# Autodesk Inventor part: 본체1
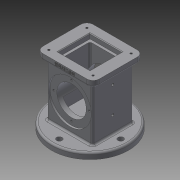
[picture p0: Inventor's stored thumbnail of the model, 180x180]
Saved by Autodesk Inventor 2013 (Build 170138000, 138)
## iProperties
Created: 2018-10
Part Number: 본체1
Material: Generic
Document SubType Name: Modeling
Designer: Administrator
Density: 1 g/cm^3
Author: Administrator
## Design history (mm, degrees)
sketch "스케치1"
  geometry: C1 r 62.5 at (0, 0); 1 further point
  constraints: 1 centre point, 1 coincident
extrude "돌출1" new body sketch "스케치1" distance "d1" = 10; taper "d2" = 0 deg
sketch "스케치2"
  geometry: C1 r 62.5 at (0, 0) reference; A1 r 50 centre (0, 0) between (0, 50) and (50, 0); 2 further points
  constraints: 4 point on circle, 1 centre point, 1 coincident
  dimensions: "d3" = 100 diameter of A1
hole "구멍1" sketch "스케치2" at (0, 50), (50, 0), (0, -50), (-50, 0) diameter "d4" = 9; stored, may be unused: countersink angle "d8" = 90 deg, drill point angle "d10" = 118 deg; dims "d5" = 6, "d6" = 4, "d7" = 2, "d9" = 8
sketch "스케치3"
  geometry: L1 (-37, 33)-(37, 33); L2 (37, 33)-(37, -33); L3 (37, -33)-(-37, -33); L4 (-37, -33)-(-37, 33); C1 r 62.5 at (0, 0) reference; 2 further points
  constraints: 8 end point, 2 midpoint, 2 parallel, 1 horizontal, 1 horizontal alignment, 1 perpendicular, 1 vertical alignment
  dimensions: "d11" = 74 distance of L1.start L1.end; "d13" = 66 distance of L1.end L2.end
extrude "돌출2" join sketch "스케치3" distance "d14" = 98; taper "d15" = 0 deg
sketch "스케치4"
  geometry: L1 (37, 33)-(-37, 33) reference; L2 (-37, 33)-(-37, -33) reference; L3 (-37, -33)-(37, -33) reference; L4 (37, -33)-(37, 33) reference; L5 (-46, 41)-(46, 41); L6 (46, 41)-(46, -41); L7 (46, -41)-(-46, -41); L8 (-46, -41)-(-46, 41); 3 further points
  constraints: 8 end point, 2 midpoint, 2 parallel, 1 horizontal, 1 horizontal alignment, 1 perpendicular, 1 vertical alignment
  dimensions: "d16" = 92 distance of L5.start L5.end; "d18" = 82 distance of L5.end L6.end
extrude "돌출3" join sketch "스케치4" distance "d19" = 10; taper "d20" = 0 deg
sketch "스케치5"
  geometry: L1 (-26, 26)-(26, 26); L2 (26, 26)-(26, -26); L3 (26, -26)-(-26, -26); L4 (-26, -26)-(-26, 26); 3 further points
  constraints: 8 end point, 2 midpoint, 2 parallel, 1 horizontal, 1 horizontal alignment, 1 perpendicular, 1 vertical alignment
  dimensions: "d21" = 52 distance of L1.start L1.end; "d23" = 52 distance of L1.end L2.end
extrude "돌출4" cut sketch "스케치5" distance "d24" = 8; taper "d25" = 0 deg
fillet "모깎기5" dims "d86" = 3
fillet "모깎기6" dims "d87" = 3
fillet "모깎기1" dims "d38" = 10
sketch "스케치8"
  geometry: L1 (-22, 22)-(22, 22); L2 (22, 22)-(22, -22); L3 (22, -22)-(-22, -22); L4 (-22, -22)-(-22, 22); 3 further points
  constraints: 8 end point, 2 midpoint, 2 parallel, 1 horizontal, 1 horizontal alignment, 1 perpendicular, 1 vertical alignment
  dimensions: "d39" = 44 distance of L1.end L2.end; "d41" = 44 distance of L1.start L1.end
extrude "돌출5" cut sketch "스케치8" distance "d42" = 74; taper "d43" = 0 deg
sketch "스케치7"
  geometry: L1 (-33, 54)-(33, 54); L2 (-62.5, 0)-(62.5, 0) reference; L3 (-33, 89)-(-30, 89); L4 (-30, 89)-(-30, 78); L5 (-30, 78)-(30, 78); L6 (30, 78)-(30, 89); L7 (30, 89)-(33, 89); L8 (33, 89)-(33, 99); L9 (-33, 99)-(-33, 89); L10 (-33, 89)-(-33, 54); L11 (33, 54)-(33, 89); 3 further points
  constraints: 20 end point, 5 parallel, 2 midpoint, 2 vertical alignment, 1 collinear, 1 horizontal, 1 perpendicular
  dimensions: "d28" = 54 distance between parallel lines of L2 L1; "d29" = 66 distance of L1.start L1.end; "d31" = 48 diameter of L5 L1; "d32" = 3 distance of L3.start L3.end; "d33" = 3 distance of L6.end L7.end; "d34" = 70 diameter of L7 L1; "d35" = 70 diameter of L3 L1; "d36" = 66 distance of L8.end L9.start; "d88" = 33 distance from line of L10 point (0, 54); "d89" = 33 distance from line of point (0, 54) L11 (derived)
revolve "회전1" sketch "스케치7" stored, may be unused: angle "d37" = 90 deg
fillet "모깎기2" dims "d44" = 3
sketch "스케치9"
  geometry: A1 r 10 centre (-36, -31) between (-46, -31) and (-36, -41) reference; A2 r 10 centre (36, -31) between (36, -41) and (46, -31) reference; A3 r 10 centre (36, 31) between (46, 31) and (36, 41) reference; A4 r 10 centre (-36, 31) between (-36, 41) and (-46, 31) reference; 1 further point
hole "구멍2" sketch "스케치9" at (-36, -31), (36, -31), (36, 31), (-36, 31) diameter "d45" = 3.242; stored, may be unused: countersink angle "d49" = 90 deg, drill point angle "d51" = 118 deg; dims "d46" = 4, "d47" = 4, "d48" = 2, "d50" = 8
sketch "스케치10"
  geometry: C1 r 35 at (0, 0) reference; A1 r 29 centre (0, 0) between (0, 29) and (29, 0); 3 further points
  constraints: 4 point on circle, 1 centre point, 1 coincident
  dimensions: "d52" = 58 diameter of A1
hole "구멍3" sketch "스케치10" at (0, 29), (29, 0), (0, -29), (-29, 0) diameter "d53" = 3.242; stored, may be unused: countersink angle "d57" = 90 deg, drill point angle "d59" = 118 deg; dims "d54" = 4, "d55" = 4, "d56" = 2, "d58" = 6
sketch "스케치11"
  geometry: L1 (13, -32.5)-(13, 92.5) reference; L2 (-95, 61)-(-95, -1) reference; L3 (13, 30)-(-95, 30); L4 (-24, -23.063)-(-24, 92.5); L5 (-67, -26.455)-(-67, 92.5); 4 further points
  constraints: 6 end point, 4 point on line, 2 coincident, 1 midpoint, 1 parallel, 1 perpendicular
  dimensions: "d60" = 37 distance between parallel lines of L1 L4; "d61" = 43 distance between parallel lines of L4 L5
hole "구멍4" sketch "스케치11" at (-67, 30), (-24, 30) diameter "d62" = 4.134; stored, may be unused: countersink angle "d66" = 90 deg, drill point angle "d68" = 118 deg; dims "d63" = 30, "d64" = 4, "d65" = 2, "d67" = 32
sketch "스케치12"
  geometry: L1 (72, 0)-(0, 0) reference; L2 (-10, 0)-(-10, -7) reference; 4 further points
  constraints: 1 other
  dimensions: "d69" = 46 distance from line of point (36, -4) L2; "d70" = 4 distance from line of point (36, -4) L1
extrude "돌출6" join sketch "스케치12" distance "d71" = 0.5; taper "d72" = 0 deg
chamfer "모따기1" distance "d73" = 1; stored, may be unused: second distance "d74" = 2, angle "d75" = 45 deg
sketch "스케치13"
  geometry: L1 (-28, 0)-(0, 0); L2 (-24.826, 18)-(0, 18); L3 (-28, 0)-(-24.826, 18); L4 (-28, 0)-(-4.799, 0); L5 (28, 0)-(49.612, 0); L6 (28, 0)-(24.826, 18); L7 (28, 0)-(48.573, 0); L8 (0, 0)-(0, 18); 1 further point
  constraints: 16 end point, 4 horizontal, 1 coincident, 1 parallel
  dimensions: "d76" = 56 distance of L1.start L5.start; "d78" = 18 distance between parallel lines of L1 L2; "d79" = 80 deg angle of L4 L3; "d82" = 28 distance of L1.start L1.end
revolve "회전2" sketch "스케치13" stored, may be unused: angle "d83" = 90 deg
fillet "모깎기3" dims "d84" = 3
fillet "모깎기4" dims "d85" = 3
node "솔리드1"
mirror "대칭1"
